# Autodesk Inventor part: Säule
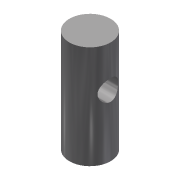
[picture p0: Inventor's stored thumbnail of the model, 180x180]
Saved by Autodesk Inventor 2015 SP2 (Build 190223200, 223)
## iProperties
Created: 2017-07
Material: 115CrV5 (Silberstahl)
Document SubType Name: Modeling
Designer: UR
Density: 7.73 g/cm^3
Appearance: Halbpoliert
Part Number: Säule
Author: UR
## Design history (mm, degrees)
sketch "Skizze1"
  geometry: L1 (0, 15)-(6, 15); L2 (6, 15)-(6, -15); L3 (6, -15)-(0, -15); L4 (0, -15)-(0, 15); 2 further points
  constraints: 8 end point, 3 perpendicular, 1 coincident, 1 horizontal, 1 midpoint
  dimensions: "d0" = 12 diameter of L2 L4; "d1" = 30 distance of L1.end L2.end
revolve "Grundkörper" sketch "Skizze1" stored, may be unused: angle "d2" = 90 deg
sketch "Skizze2"
  geometry: 1 further point
hole "Gewinde M4" sketch "Skizze2" at (0, 0) diameter "d3" = 3.242; stored, may be unused: countersink angle "d7" = 90 deg, drill point angle "d9" = 118 deg; dims "d4" = 8, "d5" = 4, "d6" = 2, "d8" = 12
workplane "Arbeitsebene1"
sketch "Skizze5"
  geometry: L1 (-6, 15)-(6, 15) reference; 2 further points
  dimensions: "d10" = 12 distance from line of point (0, 3) L1
hole "Querbohrung" sketch "Skizze5" at (0, 3) diameter "d11" = 6; stored, may be unused: countersink angle "d15" = 90 deg, drill point angle "d17" = 118 deg; dims "d12" = 4, "d13" = 4, "d14" = 2, "d16" = 8
node "Querbohrungsebene"
node "Volumenkörper1"
other parameters: "d18" = 0
